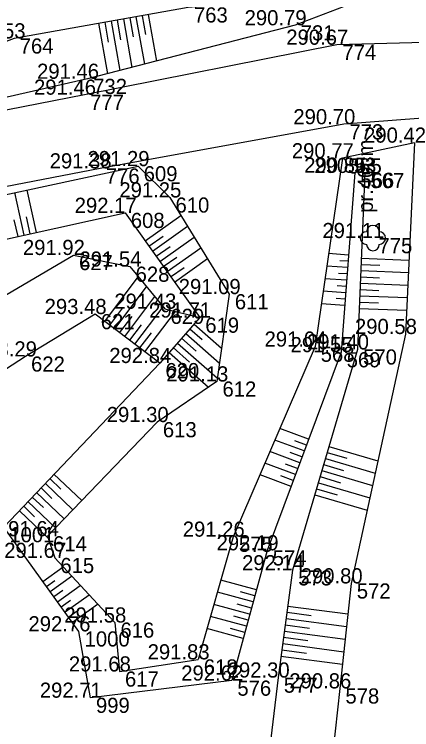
# Model space of a CAD drawing. Extents: x -599970 to -599524, y -1154772 to -1154457.
# Drawn here: x -599718.56 to -599702.82, y -1154635.85 to -1154607.5 of the extents above; entities that cross this region are included whole.
import ezdxf

# ---------------------------------------------------------------- set-up
doc = ezdxf.new("R2010")
doc.units = 0
for name, color, linetype in [('Z-PODROBNE BODY', 7, 'Continuous'), ('Z-PODROBNE BODY-CISLO', 7, 'Continuous'), ('Z-PODROBNE BODY-VYSKA', 7, 'Continuous'), ('Z-PRUMERY KMENU STROMU', 7, 'Continuous'), ('Z-SRAFOVANI SVAHU', 7, 'Continuous'), ('Z-STROMY ZNACKY KULTUR', 7, 'Continuous'), ('Z-TERENNI HRANY PATY', 7, 'Continuous'), ('Z-ZPEVNENE PLOCHY', 7, 'Continuous')]:
    doc.layers.add(name, color=color, linetype=linetype)

msp = doc.modelspace()

# ---------------------------------------------------------------- linework, layer by layer
at = {"layer": 'Z-PODROBNE BODY'}
for p, q in [((-599707.44, -1154607.94), (-599707.44, -1154607.94)), ((-599705.79, -1154608.71), (-599705.79, -1154608.71)), ((-599715.66, -1154610.06), (-599715.66, -1154610.06)), ((-599715.78, -1154610.69), (-599715.78, -1154610.69)), ((-599705.51, -1154611.86), (-599705.51, -1154611.86)), ((-599705.57, -1154613.21), (-599705.57, -1154613.21)), ((-599715.16, -1154613.61), (-599715.16, -1154613.61)), ((-599713.66, -1154613.52), (-599713.66, -1154613.52)), ((-599705.08, -1154613.78), (-599705.08, -1154613.78)), ((-599704.68, -1154613.79), (-599704.68, -1154613.79)), ((-599712.4, -1154614.76), (-599712.4, -1154614.76)), ((-599714.17, -1154615.37), (-599714.17, -1154615.37)), ((-599704.36, -1154616.37), (-599704.36, -1154616.37)), ((-599716.22, -1154617.04), (-599716.22, -1154617.04)), ((-599713.98, -1154617.5), (-599713.98, -1154617.5)), ((-599710.05, -1154618.59), (-599710.05, -1154618.59)), ((-599715.36, -1154619.38), (-599715.36, -1154619.38)), ((-599712.6, -1154619.17), (-599712.6, -1154619.17)), ((-599711.22, -1154619.52), (-599711.22, -1154619.52)), ((-599703.07, -1154620.17), (-599703.07, -1154620.17)), ((-599706.65, -1154620.67), (-599706.65, -1154620.67)), ((-599704.97, -1154620.78), (-599704.97, -1154620.78)), ((-599718.12, -1154621.06), (-599718.12, -1154621.06)), ((-599705.62, -1154620.89), (-599705.62, -1154620.89)), ((-599712.8, -1154621.32), (-599712.8, -1154621.32)), ((-599710.54, -1154622.05), (-599710.54, -1154622.05)), ((-599712.9, -1154623.66), (-599712.9, -1154623.66)), ((-599717.25, -1154628.18), (-599717.25, -1154628.18)), ((-599709.89, -1154628.2), (-599709.89, -1154628.2)), ((-599708.55, -1154628.74), (-599708.55, -1154628.74)), ((-599716.96, -1154629.04), (-599716.96, -1154629.04)), ((-599707.54, -1154629.53), (-599707.54, -1154629.53)), ((-599705.22, -1154630.05), (-599705.22, -1154630.05)), ((-599714.58, -1154631.6), (-599714.58, -1154631.6)), ((-599716, -1154631.95), (-599716, -1154631.95)), ((-599711.28, -1154633.06), (-599711.28, -1154633.06)), ((-599714.4, -1154633.54), (-599714.4, -1154633.54)), ((-599708.11, -1154633.78), (-599708.11, -1154633.78)), ((-599709.95, -1154633.9), (-599709.95, -1154633.9)), ((-599705.67, -1154634.21), (-599705.67, -1154634.21)), ((-599715.55, -1154634.58), (-599715.55, -1154634.58))]:
    msp.add_line(p, q, dxfattribs=at)
at = {"layer": 'Z-SRAFOVANI SVAHU'}
for points in [[(-599714.49, -1154607.73), (-599714.35, -1154608.51)], [(-599714.24, -1154607.69), (-599713.9, -1154609.61)], [(-599713.99, -1154607.64), (-599713.86, -1154608.4)], [(-599713.75, -1154607.6), (-599713.41, -1154609.48)], [(-599713.5, -1154607.56), (-599713.37, -1154608.3)], [(-599713.26, -1154607.51), (-599712.93, -1154609.36)], [(-599715.22, -1154607.86), (-599714.87, -1154609.86)], [(-599714.98, -1154607.82), (-599714.84, -1154608.61)], [(-599714.73, -1154607.78), (-599714.38, -1154609.73)], [(-599718.17, -1154616.26), (-599718.54, -1154614.57)], [(-599717.68, -1154616.15), (-599718.05, -1154614.47)], [(-599718.41, -1154616.31), (-599718.56, -1154615.64)], [(-599717.93, -1154616.2), (-599718.08, -1154615.53)], [(-599713.38, -1154616.48), (-599711.96, -1154615.47)], [(-599713.09, -1154616.89), (-599711.7, -1154615.9)], [(-599713.23, -1154616.69), (-599712.67, -1154616.29)], [(-599712.8, -1154617.3), (-599711.44, -1154616.33)], [(-599712.94, -1154617.09), (-599712.39, -1154616.7)], [(-599712.51, -1154617.7), (-599711.18, -1154616.76)], [(-599712.66, -1154617.5), (-599712.12, -1154617.12)], [(-599705.33, -1154617.04), (-599706.12, -1154616.98)], [(-599712.22, -1154618.11), (-599710.91, -1154617.18)], [(-599705.35, -1154617.29), (-599705.67, -1154617.27)], [(-599704.82, -1154617.16), (-599702.93, -1154617.24)], [(-599712.37, -1154617.91), (-599711.84, -1154617.53)], [(-599705.37, -1154617.54), (-599706.19, -1154617.48)], [(-599704.84, -1154617.66), (-599702.95, -1154617.73)], [(-599704.83, -1154617.41), (-599704.08, -1154617.44)], [(-599714.98, -1154619.67), (-599713.65, -1154617.9)], [(-599705.38, -1154617.79), (-599705.72, -1154617.77)], [(-599704.85, -1154617.91), (-599704.1, -1154617.94)], [(-599705.4, -1154618.04), (-599706.26, -1154617.98)], [(-599704.86, -1154618.16), (-599702.98, -1154618.23)], [(-599714.58, -1154619.97), (-599713.32, -1154618.3)], [(-599705.44, -1154618.54), (-599706.33, -1154618.47)], [(-599705.42, -1154618.29), (-599705.77, -1154618.26)], [(-599704.87, -1154618.41), (-599704.12, -1154618.44)], [(-599714.19, -1154620.27), (-599712.99, -1154618.69)], [(-599705.46, -1154618.79), (-599705.82, -1154618.76)], [(-599704.88, -1154618.66), (-599703, -1154618.73)], [(-599713.79, -1154620.57), (-599712.67, -1154619.09)], [(-599705.48, -1154619.04), (-599706.4, -1154618.97)], [(-599704.89, -1154618.91), (-599704.14, -1154618.94)], [(-599714.78, -1154619.82), (-599714.26, -1154619.13)], [(-599713.39, -1154620.87), (-599712.18, -1154619.28)], [(-599704.9, -1154619.16), (-599703.03, -1154619.23)], [(-599714.39, -1154620.12), (-599713.89, -1154619.47)], [(-599713.99, -1154620.42), (-599713.52, -1154619.81)], [(-599711.44, -1154619.78), (-599710.35, -1154620.73)], [(-599713.59, -1154620.72), (-599713.13, -1154620.12)], [(-599711.77, -1154620.15), (-599710.44, -1154621.32)], [(-599711.61, -1154619.96), (-599711.12, -1154620.39)], [(-599711.94, -1154620.34), (-599711.36, -1154620.85)], [(-599712.27, -1154620.71), (-599711.62, -1154621.28)], [(-599712.1, -1154620.53), (-599710.52, -1154621.92)], [(-599712.43, -1154620.9), (-599710.87, -1154622.28)], [(-599706.91, -1154624.33), (-599708.04, -1154623.91)], [(-599707.08, -1154624.8), (-599708.24, -1154624.37)], [(-599706.99, -1154624.57), (-599707.45, -1154624.4)], [(-599706.1, -1154624.62), (-599704.16, -1154625.19)], [(-599707.25, -1154625.27), (-599708.44, -1154624.83)], [(-599707.17, -1154625.04), (-599707.64, -1154624.86)], [(-599706.17, -1154624.86), (-599705.39, -1154625.09)], [(-599707.43, -1154625.74), (-599708.64, -1154625.29)], [(-599707.34, -1154625.5), (-599707.82, -1154625.33)], [(-599706.31, -1154625.34), (-599705.52, -1154625.58)], [(-599706.24, -1154625.1), (-599704.27, -1154625.68)], [(-599706.38, -1154625.58), (-599704.38, -1154626.17)], [(-599717.16, -1154625.9), (-599716.72, -1154626.32)], [(-599716.99, -1154625.72), (-599715.89, -1154626.77)], [(-599707.6, -1154626.21), (-599708.83, -1154625.75)], [(-599707.52, -1154625.97), (-599708, -1154625.79)], [(-599706.45, -1154625.82), (-599705.64, -1154626.06)], [(-599717.33, -1154626.09), (-599716.24, -1154627.13)], [(-599706.52, -1154626.06), (-599704.48, -1154626.66)], [(-599717.68, -1154626.45), (-599716.58, -1154627.49)], [(-599717.5, -1154626.27), (-599717.07, -1154626.68)], [(-599706.59, -1154626.3), (-599705.77, -1154626.54)], [(-599717.85, -1154626.63), (-599717.41, -1154627.04)], [(-599706.66, -1154626.54), (-599704.59, -1154627.15)], [(-599718.19, -1154626.99), (-599717.76, -1154627.41)], [(-599718.02, -1154626.81), (-599716.93, -1154627.85)], [(-599718.36, -1154627.17), (-599717.22, -1154628.26)], [(-599717.43, -1154629.97), (-599716.63, -1154629.39)], [(-599717.14, -1154630.37), (-599716.29, -1154629.76)], [(-599717.29, -1154630.17), (-599716.96, -1154629.93)], [(-599716.85, -1154630.78), (-599715.95, -1154630.13)], [(-599708.97, -1154630.3), (-599710.38, -1154629.92)], [(-599716.99, -1154630.57), (-599716.64, -1154630.32)], [(-599709.1, -1154630.78), (-599710.52, -1154630.4)], [(-599709.04, -1154630.54), (-599709.6, -1154630.39)], [(-599716.7, -1154630.98), (-599716.33, -1154630.71)], [(-599716.55, -1154631.18), (-599715.6, -1154630.5)], [(-599716.26, -1154631.59), (-599715.26, -1154630.87)], [(-599709.24, -1154631.27), (-599710.66, -1154630.88)], [(-599709.17, -1154631.03), (-599709.74, -1154630.87)], [(-599707.73, -1154630.95), (-599705.35, -1154631.26)], [(-599716.41, -1154631.39), (-599716.02, -1154631.1)], [(-599707.76, -1154631.19), (-599706.81, -1154631.32)], [(-599709.37, -1154631.75), (-599710.79, -1154631.36)], [(-599709.3, -1154631.51), (-599709.87, -1154631.35)], [(-599707.8, -1154631.44), (-599705.41, -1154631.76)], [(-599709.5, -1154632.23), (-599710.93, -1154631.84)], [(-599709.43, -1154631.99), (-599710, -1154631.84)], [(-599707.83, -1154631.69), (-599706.87, -1154631.82)], [(-599707.86, -1154631.94), (-599705.46, -1154632.26)], [(-599707.9, -1154632.18), (-599706.93, -1154632.31)], [(-599707.96, -1154632.68), (-599706.99, -1154632.81)], [(-599707.93, -1154632.43), (-599705.51, -1154632.76)], [(-599708, -1154632.93), (-599705.57, -1154633.25)]]:
    msp.add_lwpolyline(points, dxfattribs=at)
at = {"layer": 'Z-STROMY ZNACKY KULTUR'}
msp.add_circle((-599704.36, -1154616.37), 0.00025, dxfattribs=at)
for centre, start, end in [((-599704.36, -1154616.12), 0, 180), ((-599704.61, -1154616.37), 90, 270), ((-599704.11, -1154616.37), 270, 90), ((-599704.36, -1154616.62), 180, 360)]:
    msp.add_arc(centre, 0.25, start, end, dxfattribs=at)
at = {"layer": 'Z-TERENNI HRANY PATY'}
for points in [[(-599729.05, -1154602.01), (-599721.76, -1154601.98), (-599713.7, -1154601.68), (-599707.23, -1154600.75), (-599702.22, -1154599.95), (-599702.11, -1154604.78), (-599703.83, -1154606.55), (-599707.44, -1154607.94), (-599715.66, -1154610.06), (-599723.72, -1154611.89), (-599730.02, -1154613.49), (-599734.59, -1154613.85), (-599735.4, -1154613.47), (-599737.38, -1154610.51), (-599738.93, -1154607.87), (-599737.97, -1154605.84), (-599735.06, -1154604.09), (-599729.05, -1154602.01)], [(-599706.69, -1154601.61), (-599704.55, -1154601.39), (-599703.42, -1154603.18), (-599703.99, -1154604.61), (-599707.71, -1154606.89), (-599711.67, -1154607.23), (-599718.57, -1154608.46), (-599724.85, -1154610.8), (-599730.76, -1154612.67), (-599734.46, -1154612.65)], [(-599702.71, -1154612.59), (-599705.57, -1154613.21), (-599706.65, -1154620.67), (-599709.89, -1154628.2), (-599711.28, -1154633.06)], [(-599702.71, -1154612.59), (-599703.07, -1154620.17), (-599705.22, -1154630.05), (-599705.67, -1154634.21), (-599706.5, -1154641.82), (-599707.05, -1154645.89), (-599706.85, -1154650.78)], [(-599706.85, -1154650.78), (-599713.18, -1154651.03), (-599721.07, -1154652.91), (-599723.76, -1154645.8), (-599725.1, -1154640.23), (-599727.83, -1154634.18), (-599728.54, -1154633), (-599732.31, -1154631.05), (-599735.11, -1154628.08), (-599735.76, -1154623.86), (-599735.73, -1154623.89), (-599734.76, -1154621.33), (-599730.32, -1154616.62), (-599722.93, -1154615.52), (-599713.66, -1154613.52), (-599712.4, -1154614.76), (-599710.05, -1154618.59), (-599710.54, -1154622.05), (-599712.9, -1154623.66), (-599717.25, -1154628.18), (-599716.96, -1154629.04), (-599714.58, -1154631.6), (-599714.4, -1154633.54), (-599711.28, -1154633.06)], [(-599704.68, -1154613.79), (-599704.97, -1154620.78), (-599707.54, -1154629.53), (-599708.11, -1154633.78), (-599709.03, -1154641.46), (-599708.95, -1154648.47), (-599720.11, -1154645.96), (-599722.14, -1154639.54), (-599721.91, -1154632.94), (-599724.31, -1154631.24), (-599726.05, -1154627.36), (-599728.73, -1154626.15), (-599733.01, -1154625.97), (-599733.06, -1154622.51), (-599729.32, -1154618.34), (-599722.3, -1154617.17), (-599714.17, -1154615.37), (-599711.22, -1154619.52), (-599712.8, -1154621.32)], [(-599705.08, -1154613.78), (-599705.62, -1154620.89), (-599708.55, -1154628.74), (-599709.95, -1154633.9), (-599715.55, -1154634.58), (-599716, -1154631.95), (-599718.98, -1154627.82), (-599712.8, -1154621.32)], [(-599729.32, -1154618.34), (-599723.69, -1154617.7), (-599722.89, -1154620.97), (-599716.22, -1154617.04), (-599713.98, -1154617.5), (-599712.6, -1154619.17), (-599711.22, -1154619.52)], [(-599712.8, -1154621.32), (-599715.36, -1154619.38), (-599718.12, -1154621.06), (-599721.53, -1154623.26), (-599725.38, -1154619.29), (-599729.32, -1154618.34)]]:
    msp.add_lwpolyline(points, dxfattribs=at)
at = {"layer": 'Z-ZPEVNENE PLOCHY'}
for points in [[(-599671.02, -1154617.03), (-599671.63, -1154613.35), (-599675.05, -1154613.45), (-599680.32, -1154612.41), (-599686.62, -1154610.91), (-599694.45, -1154609.33), (-599700.34, -1154608.57), (-599705.79, -1154608.71), (-599715.78, -1154610.69), (-599725.58, -1154612.61), (-599730.02, -1154613.49), (-599735.64, -1154614.56), (-599743.95, -1154616.26), (-599754.96, -1154619.25), (-599762.63, -1154622.27), (-599761.65, -1154625.43)], [(-599671.02, -1154617.03), (-599674, -1154617.11), (-599674.74, -1154618.09), (-599672.97, -1154619.61), (-599672.99, -1154619.63), (-599673.43, -1154624.97), (-599672.1, -1154632.73), (-599679.37, -1154632.4), (-599679.21, -1154625.35), (-599679.14, -1154619.7), (-599679.61, -1154616.32), (-599687.06, -1154613.66), (-599695, -1154612.23), (-599700.47, -1154611.47), (-599705.51, -1154611.86), (-599715.16, -1154613.61), (-599724.96, -1154615.5), (-599735.23, -1154617.18), (-599743.14, -1154619.2), (-599754.14, -1154621.91)]]:
    msp.add_lwpolyline(points, dxfattribs=at)

# ---------------------------------------------------------------- texts
at = {"layer": 'Z-PODROBNE BODY-CISLO'}
for s, p in [(' 763', (-599711.67, -1154607.83)), (' 731', (-599707.44, -1154608.54)), (' 764', (-599718.57, -1154609.06)), (' 774', (-599705.79, -1154609.31)), (' 732', (-599715.66, -1154610.66)), (' 777', (-599715.78, -1154611.29)), (' 773', (-599705.51, -1154612.46)), (' 565', (-599705.57, -1154613.81)), (' 776', (-599715.16, -1154614.21)), (' 609', (-599713.66, -1154614.12)), (' 566', (-599705.08, -1154614.38)), (' 567', (-599704.68, -1154614.39)), (' 610', (-599712.4, -1154615.36)), (' 608', (-599714.17, -1154615.97)), (' 775', (-599704.36, -1154616.97)), (' 627', (-599716.22, -1154617.64)), (' 628', (-599713.98, -1154618.1)), (' 611', (-599710.05, -1154619.19)), (' 621', (-599715.36, -1154619.98)), (' 629', (-599712.6, -1154619.77)), (' 619', (-599711.22, -1154620.12)), (' 568', (-599706.65, -1154621.27)), (' 570', (-599704.97, -1154621.38)), (' 622', (-599718.12, -1154621.66)), (' 569', (-599705.62, -1154621.49)), (' 620', (-599712.8, -1154621.92)), (' 612', (-599710.54, -1154622.65)), (' 613', (-599712.9, -1154624.26)), (' 1001', (-599718.98, -1154628.42)), (' 614', (-599717.25, -1154628.78)), (' 575', (-599709.89, -1154628.8)), (' 574', (-599708.55, -1154629.34)), (' 615', (-599716.96, -1154629.64)), (' 573', (-599707.54, -1154630.13)), (' 572', (-599705.22, -1154630.65)), (' 616', (-599714.58, -1154632.2)), (' 1000', (-599716, -1154632.55)), (' 618', (-599711.28, -1154633.66)), (' 617', (-599714.4, -1154634.14)), (' 577', (-599708.11, -1154634.38)), (' 576', (-599709.95, -1154634.5)), (' 578', (-599705.67, -1154634.81)), (' 999', (-599715.55, -1154635.18))]:
    msp.add_text(s, height=0.6, dxfattribs=at).set_placement(p)
at = {"layer": 'Z-PODROBNE BODY-VYSKA'}
for s, p in [('290.79 ', (-599709.44, -1154607.94)), ('292.53 ', (-599720.57, -1154608.46)), ('290.67 ', (-599707.79, -1154608.71)), ('291.46 ', (-599717.66, -1154610.06)), ('291.46 ', (-599717.78, -1154610.69)), ('290.70 ', (-599707.51, -1154611.86)), ('290.42 ', (-599704.71, -1154612.59)), ('290.77 ', (-599707.57, -1154613.21)), ('291.38 ', (-599717.16, -1154613.61)), ('291.29 ', (-599715.66, -1154613.52)), ('290.85 ', (-599707.08, -1154613.78)), ('290.93 ', (-599706.68, -1154613.79)), ('291.25 ', (-599714.4, -1154614.76)), ('292.17 ', (-599716.17, -1154615.37)), ('291.11 ', (-599706.36, -1154616.37)), ('291.92 ', (-599718.22, -1154617.04)), ('291.54 ', (-599715.98, -1154617.5)), ('291.09 ', (-599712.05, -1154618.59)), ('293.48 ', (-599717.36, -1154619.38)), ('291.43 ', (-599714.6, -1154619.17)), ('291.71 ', (-599713.22, -1154619.52)), ('290.58 ', (-599705.07, -1154620.17)), ('291.04 ', (-599708.65, -1154620.67)), ('291.40 ', (-599706.97, -1154620.78)), ('293.29 ', (-599720.12, -1154621.06)), ('291.55 ', (-599707.62, -1154620.89)), ('292.84 ', (-599714.8, -1154621.32)), ('291.13 ', (-599712.54, -1154622.05)), ('291.30 ', (-599714.9, -1154623.66)), ('291.64 ', (-599719.25, -1154628.18)), ('291.26 ', (-599711.89, -1154628.2)), ('292.19 ', (-599710.55, -1154628.74)), ('291.67 ', (-599718.96, -1154629.04)), ('292.14 ', (-599709.54, -1154629.53)), ('290.80 ', (-599707.22, -1154630.05)), ('291.58 ', (-599716.58, -1154631.6)), ('292.76 ', (-599718, -1154631.95)), ('291.83 ', (-599713.28, -1154633.06)), ('291.68 ', (-599716.4, -1154633.54)), ('292.30 ', (-599710.11, -1154633.78)), ('292.62 ', (-599711.95, -1154633.9)), ('290.86 ', (-599707.67, -1154634.21)), ('292.71 ', (-599717.55, -1154634.58))]:
    msp.add_text(s, height=0.6, dxfattribs=at).set_placement(p)
at = {"layer": 'Z-PRUMERY KMENU STROMU'}
msp.add_text('pr.40cm', height=0.6, rotation=90, dxfattribs=at).set_placement((-599704.36, -1154615.37))

doc.saveas('drawing.dxf')
